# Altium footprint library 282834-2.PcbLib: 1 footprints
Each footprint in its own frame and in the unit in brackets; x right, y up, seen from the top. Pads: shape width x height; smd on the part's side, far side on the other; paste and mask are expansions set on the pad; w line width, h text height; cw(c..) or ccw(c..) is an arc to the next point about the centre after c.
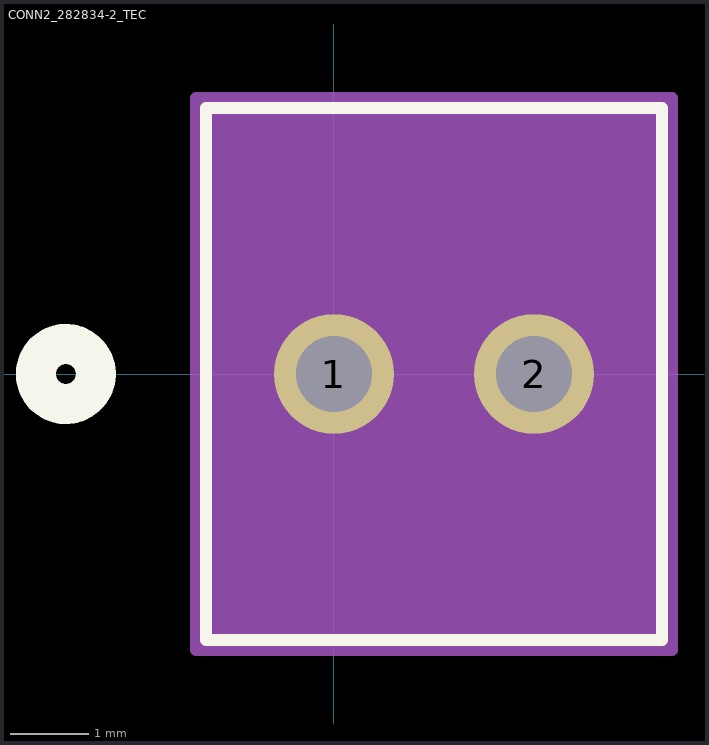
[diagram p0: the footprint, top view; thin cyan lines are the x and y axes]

## CONN2_282834-2_TEC [mil]
pads (2):
  round 60 hole 38 paste-30 mask+0: 1(0,0) 2(100,0)
Top Overlay:
  circle w20: c-134,0 r15
  lines w6: -64,-133 164,-133 164,133 -64,133 -64,-133
  text ".Designator" at -87.5,-25 h50
Bottom Overlay:
  circle w20: c-134,0 r15
Mechanical 13:
  circle w20: c0,-75 r15
  lines w1: -59,-128 159,-128 159,128 -59,128 -59,-128
  text ".Designator" at -87.5,-25 h50
Mechanical 15:
  region: 169,138 -69,138 -69,-138 169,-138
  lines w6: -69,-138 -69,138 169,138 169,-138 -69,-138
